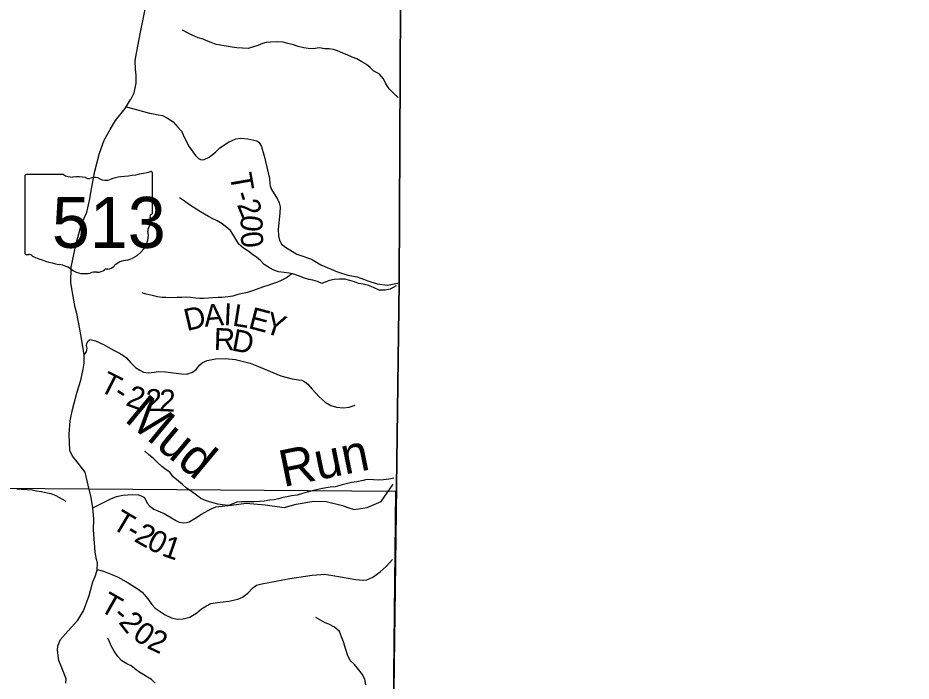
# Model space of a CAD drawing. Extents: x 2043100 to 2470832, y 443715 to 810583.
# Drawn here: x 2296048 to 2308244, y 658375 to 667437 of the extents above; entities that cross this region are included whole.
import ezdxf

# ---------------------------------------------------------------- set-up
doc = ezdxf.new("R2010")
doc.units = 0
for name, color, linetype in [('GM_X_Adjacent_County', 7, 'Continuous'), ('GM_X_County', 7, 'Continuous'), ('GM_X_Minor_River', 7, 'Continuous'), ('GM_X_Minor_River_Text', 7, 'Continuous'), ('GM_X_Section', 7, 'Continuous'), ('GM_X_State_Location', 7, 'Continuous'), ('GM_X_State_Route', 7, 'Continuous'), ('GM_X_State_Shield', 7, 'Continuous'), ('GM_X_Township', 7, 'Continuous'), ('GM_X_Township_Road', 7, 'Continuous'), ('GM_X_Township_Road_Text', 7, 'Continuous'), ('GM_X_Township_ROW', 7, 'Continuous')]:
    doc.layers.add(name, color=color, linetype=linetype)

msp = doc.modelspace()

# ---------------------------------------------------------------- linework, layer by layer
at = {"layer": 'GM_X_Adjacent_County'}
msp.add_lwpolyline([(2300714, 629163), (2300774, 635425), (2300814, 639567), (2300926, 645360), (2300953, 646723), (2300982, 648198), (2301002, 649256), (2301016, 650156), (2301098, 653379), (2301153, 655541), (2301153, 656155), (2301254, 663815), (2301288, 670486), (2301311, 672396), (2301315, 672683), (2301334, 673782), (2301360, 674291), (2301434, 679295), (2301452, 681110), (2301478, 683091), (2302497, 683068), (2305696, 683037), (2309205, 683004)], dxfattribs=at)
at = {"layer": 'GM_X_County'}
msp.add_lwpolyline([(2309205, 683004), (2305696, 683037), (2302497, 683068), (2301478, 683091), (2301452, 681110), (2301434, 679295), (2301360, 674291), (2301334, 673782), (2301315, 672683), (2301311, 672396), (2301288, 670486), (2301254, 663815), (2301153, 656155), (2301153, 655541), (2301098, 653379), (2301016, 650156), (2301002, 649256), (2300982, 648198), (2300953, 646723), (2300926, 645360), (2300814, 639567), (2300774, 635425), (2300714, 629163)], dxfattribs=at)
at = {"layer": 'GM_X_Minor_River'}
for points in [[(2301242, 666350), (2301177, 666410), (2301117, 666468), (2301074, 666534), (2301042, 666604), (2300983, 666672), (2300907, 666711), (2300857, 666757), (2300807, 666801), (2300745, 666836), (2300674, 666876), (2300610, 666902), (2300544, 666931), (2300484, 666955), (2300410, 666989), (2300358, 667004), (2300296, 667016), (2300238, 667016), (2300162, 667027), (2300086, 667013), (2300010, 667020), (2299954, 667028), (2299876, 667048), (2299812, 667067), (2299736, 667089), (2299670, 667103), (2299590, 667110), (2299498, 667106), (2299438, 667101), (2299386, 667085), (2299326, 667060), (2299253, 667036), (2299193, 667018), (2299115, 667021), (2299037, 667029), (2298973, 667036), (2298917, 667046), (2298863, 667056), (2298813, 667063), (2298757, 667075), (2298687, 667099), (2298627, 667122), (2298576, 667146), (2298510, 667166), (2298418, 667207), (2298364, 667233), (2298296, 667267)], [(2301211, 663775), (2301133, 663730), (2301061, 663716), (2300983, 663718), (2300905, 663753), (2300833, 663779), (2300761, 663798), (2300700, 663810), (2300644, 663832), (2300580, 663847), (2300510, 663865), (2300440, 663869), (2300368, 663864), (2300305, 663848), (2300251, 663829), (2300197, 663809), (2300137, 663837), (2300073, 663852), (2300019, 663862), (2299949, 663886), (2299891, 663907), (2299804, 663939), (2299754, 663949), (2299682, 663958), (2299608, 663968), (2299544, 663990), (2299484, 664023), (2299410, 664069), (2299362, 664121), (2299307, 664166), (2299257, 664200), (2299203, 664244), (2299127, 664292), (2299067, 664347), (2298998, 664459), (2298952, 664533), (2298899, 664575), (2298835, 664621), (2298769, 664662), (2298711, 664692), (2298649, 664724), (2298596, 664753), (2298542, 664789), (2298490, 664819), (2298390, 664883), (2298322, 664932), (2298255, 664976)], [(2299788, 663942), (2299717, 663884), (2299645, 663850), (2299591, 663827), (2299523, 663801), (2299460, 663779), (2299400, 663760), (2299336, 663738), (2299266, 663713), (2299184, 663685), (2299114, 663672), (2299051, 663656), (2298981, 663635), (2298917, 663625), (2298837, 663618), (2298781, 663618), (2298707, 663614), (2298651, 663609), (2298583, 663601), (2298531, 663601), (2298471, 663606), (2298405, 663616), (2298349, 663620), (2298285, 663617), (2298217, 663615), (2298138, 663612), (2298070, 663618), (2298014, 663618), (2297956, 663625), (2297880, 663643), (2297800, 663664), (2297743, 663680)], [(2301179, 661147), (2301112, 661133), (2301040, 661126), (2300972, 661122), (2300902, 661127), (2300814, 661129), (2300762, 661117), (2300677, 661100), (2300603, 661088), (2300529, 661071), (2300477, 661059), (2300379, 661030), (2300313, 661024), (2300205, 661009), (2300142, 660995), (2300084, 660978), (2300000, 660956), (2299936, 660939), (2299860, 660915), (2299782, 660908), (2299726, 660894), (2299667, 660882), (2299613, 660867), (2299547, 660851), (2299487, 660846), (2299411, 660834), (2299347, 660829), (2299275, 660823), (2299209, 660823), (2299153, 660826), (2299099, 660826), (2299039, 660822), (2298982, 660799), (2298922, 660773), (2298844, 660782), (2298780, 660794), (2298730, 660806), (2298664, 660825), (2298610, 660841), (2298547, 660871), (2298487, 660914), (2298419, 660968), (2298345, 661018), (2298295, 661062), (2298242, 661105), (2298170, 661167), (2298124, 661231), (2298072, 661263), (2298013, 661307), (2297959, 661358), (2297903, 661410), (2297832, 661472), (2297782, 661518)], [(2296035, 661004), (2296095, 660996), (2296175, 660993), (2296243, 660987), (2296301, 660975), (2296369, 660966), (2296429, 660952), (2296499, 660937), (2296567, 660909), (2296641, 660871), (2296701, 660832)], [(2300801, 658325), (2300784, 658401), (2300748, 658471), (2300704, 658529), (2300643, 658601), (2300583, 658656), (2300547, 658736), (2300528, 658808), (2300492, 658912), (2300465, 658978), (2300439, 659052), (2300371, 659114), (2300294, 659154), (2300244, 659171), (2300178, 659207), (2300114, 659245)], [(2297923, 658348), (2297871, 658395), (2297820, 658431), (2297768, 658463), (2297714, 658493), (2297664, 658530), (2297594, 658582), (2297536, 658610), (2297467, 658654), (2297413, 658713), (2297363, 658785), (2297324, 658849), (2297302, 658901), (2297274, 658963)]]:
    msp.add_lwpolyline(points, dxfattribs=at)
at = {"layer": 'GM_X_Section'}
msp.add_lwpolyline([(2295826, 661012), (2301204, 660969), (2301144, 655551), (2295815, 655607)], close=True, dxfattribs=at)
at = {"layer": 'GM_X_State_Route'}
for points in [[(2297661, 666668), (2297661, 666669), (2297658, 666679), (2297650, 666834), (2297654, 666884), (2297721, 667240), (2297752, 667396), (2297784, 667557)], [(2296701, 658345), (2296705, 658404), (2296649, 658558), (2296608, 658655), (2296587, 658800), (2296593, 658856), (2296632, 658944), (2296733, 659061), (2296866, 659206), (2296943, 659337), (2297020, 659547), (2297070, 659732), (2297101, 659806), (2297130, 659891), (2297131, 659901), (2297134, 659991), (2297121, 660035), (2297101, 660137), (2297081, 660442), (2297087, 660592), (2297073, 660744), (2297047, 660883), (2297007, 661054), (2296967, 661228), (2296840, 661392), (2296795, 661449), (2296756, 661525), (2296747, 661748), (2296763, 661931), (2296792, 662088), (2296856, 662327), (2296907, 662488), (2296940, 662635), (2296953, 662721), (2296955, 662833), (2296916, 663054), (2296893, 663185), (2296855, 663398), (2296830, 663481), (2296810, 663578), (2296772, 663816), (2296775, 664031), (2296843, 664354), (2296915, 664618), (2296988, 664781), (2297024, 664944), (2297051, 665101), (2297097, 665342), (2297163, 665587), (2297228, 665767), (2297309, 665910), (2297381, 666035), (2297514, 666199), (2297527, 666222), (2297585, 666322), (2297595, 666332), (2297634, 666414), (2297661, 666547), (2297664, 666659), (2297661, 666668)]]:
    msp.add_lwpolyline(points, dxfattribs=at)
at = {"layer": 'GM_X_State_Shield'}
for p, q in [((2296144, 665277), (2296144, 664220)), ((2296671, 665295), (2296161, 665295)), ((2297884, 664769), (2297884, 665321)), ((2297884, 664769), (2297884, 664769))]:
    msp.add_line(p, q, dxfattribs=at)
for centre, major_axis, start_param, end_param in [((2297264, 666736), (1845, 0), 4.814394, 5.042369), ((2297865, 665324), (19.4, 0), 6.141152, 7.989035), ((2296164, 665279), (20.2, 0), 1.712693, 3.28349), ((2296792, 665418), (196, 0), 4.042523, 4.731795), ((2296857, 664702), (702, 0), 1.404758, 1.657858), ((2297016, 665285), (56.4, 0), 3.836095, 5.185415), ((2297099, 665163), (117, 0), 0.950623, 2.079405), ((2297251, 665330), (141, 0), 4.081561, 5.145723), ((2297500, 664973), (371, 0), 1.699011, 2.107814), ((2297880, 664728), (30, 0), 1.883978, 3.671073), ((2297689, 664658), (180, 0), 5.934695, 6.695948), ((2297864, 664767), (20.7, 0), 5.05454, 6.418171), ((2297954, 664537), (131, 0), 2.387724, 3.262537), ((2297368, 664467), (462, 0), 5.101752, 6.440018), ((2296164, 664218), (20.3, 0), 3.00124, 4.508301), ((2296167, 664326), (155, 0), 4.665946, 4.897461), ((2296199, 664160), (56, 0), 0.519207, 1.627899), ((2296906, 665109), (1333, 0), 4.195997, 4.488961), ((2297562, 663924), (253, 0), 1.647645, 2.488434), ((2296508, 663746), (417, 0), 0.823519, 1.323587), ((2296959, 664154), (265, 0), 4.026481, 4.996735), ((2297131, 664075), (141, 0), 4.691044, 5.507374), ((2297259, 663973), (39.7, 0), 1.147584, 2.315152), ((2297242, 664118), (149, 0), 4.937069, 5.64225), ((2297112, 663789), (217, 0), 1.495662, 1.94098)]:
    msp.add_ellipse(centre, major_axis=major_axis, ratio=0.8, start_param=start_param, end_param=end_param, dxfattribs=at)
at = {"layer": 'GM_X_Township'}
msp.add_lwpolyline([(2301434, 679295), (2301360, 674291), (2301334, 673782), (2301315, 672683), (2301311, 672396), (2301288, 670486), (2301254, 663815), (2301153, 656155)], dxfattribs=at)
at = {"layer": 'GM_X_Township_Road'}
for points in [[(2297527, 666222), (2297679, 666180), (2297845, 666137), (2297899, 666124), (2297964, 666112), (2298022, 666101), (2298092, 666069), (2298167, 666018), (2298233, 665944), (2298280, 665887), (2298305, 665841), (2298378, 665691), (2298471, 665557), (2298516, 665516), (2298550, 665498), (2298590, 665500), (2298662, 665535), (2298745, 665600), (2298807, 665661), (2298922, 665740), (2299022, 665783), (2299090, 665795), (2299186, 665786), (2299311, 665757), (2299343, 665734), (2299373, 665680), (2299378, 665672), (2299381, 665659)], [(2299381, 665659), (2299409, 665552), (2299469, 665301), (2299482, 665243), (2299488, 665171), (2299493, 665141), (2299513, 665093), (2299594, 664958), (2299615, 664908), (2299627, 664855), (2299624, 664767), (2299602, 664548), (2299605, 664460), (2299621, 664398), (2299648, 664346), (2299702, 664303), (2299858, 664210), (2299912, 664192), (2300044, 664147), (2300079, 664127), (2300183, 664064), (2300410, 663966), (2300551, 663923), (2300681, 663898), (2300730, 663880), (2300826, 663843), (2300953, 663804), (2301093, 663783), (2301254, 663815)], [(2296955, 662833), (2296986, 662876), (2296993, 662926), (2296987, 662962), (2296989, 662990), (2297006, 663025), (2297034, 663043), (2297109, 663026), (2297219, 662974), (2297282, 662937), (2297362, 662894), (2297437, 662856), (2297481, 662830), (2297531, 662791), (2297586, 662727), (2297655, 662661), (2297713, 662624), (2297763, 662598), (2297825, 662589), (2297908, 662595), (2297964, 662606), (2298064, 662603), (2298280, 662575), (2298356, 662569), (2298434, 662594), (2298484, 662633), (2298533, 662697), (2298567, 662728), (2298631, 662756), (2298747, 662777), (2298879, 662783), (2299019, 662770), (2299218, 662721), (2299335, 662674), (2299636, 662547), (2299791, 662504), (2299879, 662491), (2299925, 662485), (2299968, 662463), (2300006, 662432), (2300067, 662366), (2300162, 662260), (2300242, 662187), (2300323, 662140), (2300397, 662116), (2300494, 662107), (2300570, 662120), (2300651, 662147)], [(2297073, 660744), (2297200, 660806), (2297318, 660865), (2297394, 660898), (2297480, 660916), (2297614, 660923), (2297696, 660918), (2297732, 660906), (2297779, 660882), (2297815, 660806), (2297848, 660764), (2297906, 660726), (2298045, 660665), (2298147, 660606), (2298214, 660564), (2298252, 660546), (2298310, 660539), (2298348, 660541), (2298386, 660553), (2298466, 660598), (2298555, 660657), (2298687, 660730), (2298753, 660756), (2298877, 660770), (2298878, 660770)], [(2298878, 660770), (2298963, 660780), (2299165, 660807), (2299426, 660785), (2299685, 660745), (2299849, 660794), (2300087, 660834), (2300257, 660831), (2300480, 660774), (2300552, 660749)], [(2297131, 659901), (2297217, 659875), (2297331, 659832), (2297416, 659796), (2297552, 659717), (2297691, 659632), (2297746, 659590), (2297824, 659500), (2297875, 659422), (2297923, 659373), (2298058, 659279), (2298147, 659240), (2298223, 659222), (2298305, 659227), (2298397, 659249), (2298491, 659308), (2298557, 659361), (2298622, 659403), (2298684, 659434), (2298772, 659449), (2298926, 659466), (2299051, 659495), (2299114, 659521), (2299186, 659578), (2299256, 659650), (2299308, 659685), (2299378, 659703), (2299762, 659778), (2300066, 659823), (2300184, 659831), (2300232, 659836), (2300348, 659816), (2300663, 659762), (2300764, 659753), (2300814, 659759), (2300895, 659796), (2300995, 659867), (2301075, 659942), (2301161, 660037)]]:
    msp.add_lwpolyline(points, dxfattribs=at)
at = {"layer": 'GM_X_Township_ROW'}
msp.add_lwpolyline([(2300552, 660749), (2300552, 660749), (2300641, 660719), (2300815, 660746), (2301010, 660828), (2301174, 661064)], dxfattribs=at)

# ---------------------------------------------------------------- texts
at = {"layer": 'GM_X_Minor_River_Text'}
for s, height, rotation, p in [('Mud', 500.1, 320.3079, (2297488, 661937)), ('Run', 500, 11.5103, (2299672, 661025))]:
    msp.add_text(s, height=height, rotation=rotation, dxfattribs=at).set_placement(p)
at = {"layer": 'GM_X_State_Location'}
msp.add_text('513', height=0.0000833, rotation=0, dxfattribs=at).set_placement((2296641, 664606))
for s in ['s', 'r']:
    msp.add_text(s, height=0.0000833, dxfattribs=at).set_placement((2296995, 664679))
at = {"layer": 'GM_X_State_Shield'}
msp.add_text('513', height=696.1, dxfattribs=at).set_placement((2296513, 664295))
at = {"layer": 'GM_X_Township_Road_Text'}
for s, rotation, p in [('T', 279.8238, (2298939, 665293)), ('2', 292.321, (2299035, 664886)), ('-', 287.8457, (2298989, 665027)), ('0', 265.0133, (2299100, 664752)), ('0', 276.3149, (2299084, 664503)), ('A', 5.114, (2298601, 663216)), ('I', 357.4623, (2298853, 663239)), ('L', 350.9322, (2298967, 663234)), ('D', 13.2163, (2298355, 663157)), ('E', 345.1384, (2299181, 663201)), ('Y', 341.9982, (2299394, 663144)), ('R', 358.3332, (2298720, 662901)), ('D', 349.3902, (2298954, 662895)), ('T', 333.0459, (2297143, 662350)), ('2', 339.8604, (2297507, 662149)), ('-', 326.2212, (2297335, 662253)), ('2', 359.2805, (2297789, 662066)), ('2', 358.095, (2297972, 662063)), ('T', 329.3222, (2297313, 660474)), ('-', 329.8282, (2297508, 660358)), ('2', 331.1177, (2297621, 660292)), ('0', 332.2969, (2297789, 660200)), ('1', 340.9832, (2297998, 660094)), ('T', 330.413, (2297146, 659346)), ('-', 320.3673, (2297329, 659243)), ('2', 308.3209, (2297413, 659177)), ('0', 325.4159, (2297598, 658965)), ('2', 334.5886, (2297796, 658834))]:
    msp.add_text(s, height=300, rotation=rotation, dxfattribs=at).set_placement(p)

doc.saveas('drawing.dxf')
